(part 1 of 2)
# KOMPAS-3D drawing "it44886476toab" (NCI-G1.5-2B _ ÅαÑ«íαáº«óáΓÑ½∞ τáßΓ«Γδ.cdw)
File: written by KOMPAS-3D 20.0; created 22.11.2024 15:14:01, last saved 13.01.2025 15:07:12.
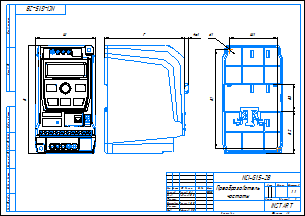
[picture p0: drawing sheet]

Sheet 1: A3, landscape

Document properties: Полное имя файла: P:\INSTART\Технический отдел\ОР\Прочие задачи\КД на номенклатурный ряд\КД на типоразмеры ПЧ\NCI\NCI-G1.5-2B\NCI-G1.5-2B _ Преобразователь частоты.cdw; Автор: admin

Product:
- Part/product: it44886476toab
    Масса: 2.32322
  - Body: Тело 2
      Масса: 0.00113358
  - Body: Тело 3
      Масса: 0.00113358
  - Body: Тело 4
      Масса: 0.000355433
  - Body: Тело 6
      Масса: 0.000355433
  - Body: Тело 7
      Масса: 0.000703761
  - Body: Тело 8
      Масса: 0.000703761
  - Body: Тело 10
      Масса: 0.0160396
  - Body: Тело 11
      Масса: 0.000703761
  - Body: Тело 13
      Масса: 0.000703761
  - Body: Тело 14
      Масса: 0.000703761
  - Body: Тело 18
      Масса: 0.0117014
  - Body: Тело 20
      Масса: 0.120334
  - Body: Тело 21
      Масса: 0.0864411
  - Body: Тело 22
      Масса: 0.0636504
  - Body: Тело 25
      Масса: 0.00135688
  - Body: Тело 26
      Масса: 0.00135688
  - Body: Тело 27
      Масса: 0.00135688
  - Body: Тело 30
      Масса: 0.000935996
  - Body: Тело 34
      Масса: 0.00831628
  - Body: Тело 36
      Масса: 0.0668131
  - Body: Тело 37
      Масса: 0.0343584
  - Body: Тело 39
      Масса: 0.0119524
  - Body: Тело 40
      Масса: 0.0119524
  - Body: Тело 42
      Масса: 0.0119524
  - Body: Тело 43
      Масса: 0.0119524
  - Body: Тело 46
      Масса: 0.0119034
  - Body: Тело 47
      Масса: 0.551587
  - Body: Тело 51
      Масса: 1.32696e-05
  - Body: Тело 54
      Масса: 1.32696e-05
  - Body: Тело 55
      Масса: 1.32696e-05
  - Body: Тело 56
      Масса: 1.32696e-05
  - Body: Тело 58
      Масса: 1.32696e-05
  - Body: Тело 61
      Масса: 1.32696e-05
  - Body: Тело 57
      Масса: 1.32696e-05
  - Body: Тело 63
      Масса: 1.65581e-05
  - Body: Тело 66
      Масса: 1.65581e-05
  - Body: Тело 67
      Масса: 1.65581e-05
  - Body: Тело 68
      Масса: 1.65581e-05
  - Body: Тело 69
      Масса: 1.65581e-05
  - Body: Тело 73
      Масса: 1.65581e-05
  - Body: Тело 48
      Масса: 0.00853877
  - Body: Тело 74
      Масса: 1.65581e-05
  - Body: Тело 78
      Масса: 1.65581e-05
  - Body: Тело 79
      Масса: 1.32696e-05
  - Body: Тело 80
      Масса: 1.32696e-05
  - Body: Тело 82
      Масса: 1.32696e-05
  - Body: Тело 83
      Масса: 1.32696e-05
  - Body: Тело 84
      Масса: 1.32696e-05
  - Body: Тело 87
      Масса: 0.000966482
  - Body: Тело 88
      Масса: 0.000873873
  - Body: Тело 15
      Масса: 0.000703761
  - Body: Тело 91
      Масса: 0.0246688
  - Body: Тело 92
      Масса: 3.83377e-05
  - Body: Тело 94
      Масса: 0.00554276
  - Body: Тело 96
      Масса: 0.00181049
  - Body: Тело 101
      Масса: 1.32696e-05
  - Body: Тело 90
      Масса: 0.000966482
  - Body: Тело 102
      Масса: 1.32696e-05
  - Body: Тело 104
      Масса: 1.32696e-05
  - Body: Тело 107
      Масса: 1.32696e-05
  - Body: Тело 108
      Масса: 1.32696e-05
  - Body: Тело 111
      Масса: 0.000194606
  - Body: Тело 115
      Масса: 0.000413213
  - Body: Тело 123
      Масса: 1.65581e-05
  - Body: Тело 127
      Масса: 1.32696e-05
  - Body: Тело 128
      Масса: 1.32696e-05
  - Body: Тело 129
      Масса: 1.32696e-05
  - Body: Тело 112
      Масса: 0.000413213
  - Body: Тело 130
      Масса: 1.32696e-05
  - Body: Тело 16
      Масса: 0.000703761
  - Body: Тело 131
      Масса: 1.32696e-05
  - Body: Тело 132
      Масса: 1.32696e-05
  - Body: Тело 133
      Масса: 1.32696e-05
  - Body: Тело 38
      Масса: 0.00631989
  - Body: Тело 135
      Масса: 1.32696e-05
  - Body: Тело 136
      Масса: 1.32696e-05
  - Body: Тело 142
      Масса: 0.000213463
  - Body: Тело 144
      Масса: 1.32696e-05
  - Body: Тело 62
      Масса: 1.32696e-05
  - Body: Тело 24
      Масса: 0.0110484
  - Body: Тело 147
      Масса: 1.32696e-05
  - Body: Тело 148
      Масса: 1.32696e-05
  - Body: Тело 154
      Масса: 1.32696e-05
  - Body: Тело 156
      Масса: 1.32696e-05
  - Body: Тело 158
      Масса: 1.32696e-05
  - Body: Тело 116
      Масса: 0.000413213
  - Body: Тело 159
      Масса: 1.32696e-05
  - Body: Тело 165
      Масса: 1.65581e-05
  - Body: Тело 166
      Масса: 1.32696e-05
  - Body: Тело 140
      Масса: 0.000213463
  - Body: Тело 169
      Масса: 1.32696e-05
  - Body: Тело 171
      Масса: 1.32696e-05
  - Body: Тело 153
      Масса: 1.32696e-05
  - Body: Тело 172
      Масса: 1.65581e-05
  - Body: Тело 173
      Масса: 1.32696e-05
  - Body: Тело 137
      Масса: 1.32696e-05
  - Body: Тело 45
      Масса: 0.0267013
  - Body: Тело 175
      Масса: 1.32696e-05
  - Body: Тело 177
      Масса: 1.32696e-05
  - Body: Тело 50
      Масса: 0.00101975
  - Body: Тело 44
      Масса: 0.0119524
  - Body: Тело 178
      Масса: 1.32696e-05
  - Body: Тело 179
      Масса: 1.32696e-05
  - Body: Тело 181
      Масса: 1.32696e-05
  - Body: Тело 182
      Масса: 1.32696e-05
  - Body: Тело 183
      Масса: 1.32696e-05
  - Body: Тело 188
      Масса: 1.32696e-05
  - Body: Тело 189
      Масса: 1.32696e-05
  - Body: Тело 192
      Масса: 1.32696e-05
  - Body: Тело 195
      Масса: 1.32696e-05
  - Body: Тело 197
      Масса: 1.32696e-05
  - Body: Тело 198
      Масса: 1.32696e-05
  - Body: Тело 199
      Масса: 1.32696e-05
  - Body: Тело 29
      Масса: 0.00135688
  - Body: Тело 201
      Масса: 1.32696e-05
  - Body: Тело 202
      Масса: 1.32696e-05
  - Body: Тело 205
      Масса: 1.32696e-05
  - Body: Тело 208
      Масса: 1.7366e-05
  - Body: Тело 209
      Масса: 1.32696e-05
  - Body: Тело 211
      Масса: 1.32696e-05
  - Body: Тело 212
      Масса: 1.32696e-05
  - Body: Тело 214
      Масса: 1.32696e-05
  - Body: Тело 9
      Масса: 0.000703761
  - Body: Тело 215
      Масса: 1.65581e-05
  - Body: Тело 217
      Масса: 1.32696e-05
  - Body: Тело 218
      Масса: 1.32696e-05
  - Body: Тело 219
      Масса: 1.32696e-05
  - Body: Тело 220
      Масса: 1.32696e-05
  - Body: Тело 221
      Масса: 1.65581e-05
  - Body: Тело 223
      Масса: 1.32696e-05
  - Body: Тело 162
      Масса: 1.65581e-05
  - Body: Тело 224
      Масса: 1.32696e-05
  - Body: Тело 228
      Масса: 1.32696e-05
  - Body: Тело 184
      Масса: 1.32696e-05
  - Body: Тело 230
      Масса: 1.32696e-05
  - Body: Тело 231
      Масса: 0.00398049
  - Body: Тело 232
      Масса: 5.48304e-05
  - Body: Тело 233
      Масса: 1.7366e-05
  - Body: Тело 1
      Масса: 0.00113358
  - Body: Тело 237
      Масса: 1.7366e-05
  - Body: Тело 141
      Масса: 0.000213463
  - Body: Тело 241
      Масса: 0.000424983
  - Body: Тело 65
      Масса: 1.65581e-05
  - Body: Тело 242
      Масса: 1.65581e-05
  - Body: Тело 243
      Масса: 1.65581e-05
  - Body: Тело 245
      Масса: 1.65581e-05
  - Body: Тело 234
      Масса: 1.7366e-05
  - Body: Тело 114
      Масса: 0.000413213
  - Body: Тело 19
      Масса: 0.0117014
  - Body: Тело 248
      Масса: 1.7366e-05
  - Body: Тело 249
      Масса: 1.7366e-05
  - Body: Тело 250
      Масса: 1.7366e-05
  - Body: Тело 254
      Масса: 1.32696e-05
  - Body: Тело 255
      Масса: 1.7366e-05
  - Body: Тело 119
      Масса: 0.000413213
  - Body: Тело 256
      Масса: 1.7366e-05
  - Body: Тело 167
      Масса: 1.32696e-05
  - Body: Тело 260
      Масса: 1.7366e-05
  - Body: Тело 261
      Масса: 3.83377e-05
  - Body: Тело 170
      Масса: 1.32696e-05
  - Body: Тело 463
      Масса: 0.000404362
  - Body: Тело 226
      Масса: 0.000413213
  - Body: Тело 464
      Масса: 0.00829425
  - Body: Тело 268
      Масса: 5.48304e-05
  - Body: Тело 467
      Масса: 0.00436982
  - Body: Тело 475
      Масса: 1.51773e-05
  - Body: Тело 451
      Масса: 6.34685e-05
  - Body: Тело 478
      Масса: 1.51773e-05
  - Body: Тело 465
      Масса: 0.00829114
  - Body: Тело 383
      Масса: 0.000340816
  - Body: Тело 125
      Масса: 1.65581e-05
  - Body: Тело 643
      Масса: 0.000158536
  - Body: Тело 514
      Масса: 1.51773e-05
  - Body: Тело 483
      Масса: 1.51773e-05
  - Body: Тело 486
      Масса: 0.000158536
  - Body: Тело 581
      Масса: 1.65581e-05
  - Body: Тело 490
      Масса: 1.51773e-05
  - Body: Тело 491
      Масса: 1.65581e-05
  - Body: Тело 433
      Масса: 0.000118347
  - Body: Тело 496
      Масса: 1.51773e-05
  - Body: Тело 437
      Масса: 0.00113358
  - Body: Тело 535
      Масса: 1.52051e-05
  - Body: Тело 498
      Масса: 1.51773e-05
  - Body: Тело 60
      Масса: 1.32696e-05
  - Body: Тело 369
      Масса: 1.32696e-05
  - Body: Тело 501
      Масса: 1.51773e-05
  - Body: Тело 503
      Масса: 1.51773e-05
  - Body: Тело 447
      Масса: 0.000307437
  - Body: Тело 187
      Масса: 1.32696e-05
  - Body: Тело 12
      Масса: 0.000703761
  - Body: Тело 507
      Масса: 1.51773e-05
  - Body: Тело 174
      Масса: 1.65581e-05
  - Body: Тело 587
      Масса: 1.32696e-05
  - Body: Тело 155
      Масса: 1.32696e-05
  - Body: Тело 512
      Масса: 1.51773e-05
  - Body: Тело 515
      Масса: 0.00507372
  - Body: Тело 510
      Масса: 1.51773e-05
  - Body: Тело 487
      Масса: 1.65581e-05
  - Body: Тело 432
      Масса: 0.000118347
  - Body: Тело 524
      Масса: 1.65581e-05
  - Body: Тело 637
      Масса: 1.51773e-05
  - Body: Тело 519
      Масса: 1.7366e-05
  - Body: Тело 427
      Масса: 1.32696e-05
  - Body: Тело 520
      Масса: 5.48304e-05
  - Body: Тело 326
      Масса: 1.32696e-05
  - Body: Тело 509
      Масса: 1.51773e-05
  - Body: Тело 571
      Масса: 0.00166679
  - Body: Тело 521
      Масса: 1.32696e-05
  - Body: Тело 522
      Масса: 1.65581e-05
  - Body: Тело 49
      Масса: 0.00944
  - Body: Тело 319
      Масса: 1.32696e-05
  - Body: Тело 458
      Масса: 1.51773e-05
  - Body: Тело 523
      Масса: 0.000255388
  - Body: Тело 191
      Масса: 1.32696e-05
  - Body: Тело 590
      Масса: 1.32696e-05
  - Body: Тело 599
      Масса: 7.12116e-06
  - Body: Тело 528
      Масса: 0.000141095
  - Body: Тело 64
      Масса: 1.65581e-05
  - Body: Тело 468
      Масса: 0.0253857
  - Body: Тело 216
      Масса: 0.000280294
  - Body: Тело 443
      Масса: 0.00113358
  - Body: Тело 239
      Масса: 5.48304e-05
  - Body: Тело 200
      Масса: 1.32696e-05
  - Body: Тело 579
      Масса: 0.00017125
  - Body: Тело 529
      Масса: 5.61948e-05
  - Body: Тело 493
      Масса: 1.51773e-05
  - Body: Тело 532
      Масса: 5.61948e-05
  - Body: Тело 343
      Масса: 0.00166679
  - Body: Тело 616
      Масса: 1.63919e-05
  - Body: Тело 462
      Масса: 0.000404362
  - Body: Тело 542
      Масса: 0.000158536
  - Body: Тело 543
      Масса: 0.000158536
  - Body: Тело 615
      Масса: 1.63919e-05
  - Body: Тело 149
      Масса: 1.32696e-05
  - Body: Тело 146
      Масса: 1.32696e-05
  - Body: Тело 469
      Масса: 0.0113891
  - Body: Тело 544
      Масса: 0.000158536
  - Body: Тело 295
      Масса: 1.65581e-05
  - Body: Тело 120
      Масса: 0.000413213
  - Body: Тело 352
      Масса: 2.90876e-05
  - Body: Тело 502
      Масса: 1.51773e-05
  - Body: Тело 461
      Масса: 0.000404362
  - Body: Тело 145
      Масса: 1.32696e-05
  - Body: Тело 545
      Масса: 1.51773e-05
  - Body: Тело 506
      Масса: 1.51773e-05
  - Body: Тело 71
      Масса: 1.65581e-05
  - Body: Тело 41
      Масса: 0.0119524
  - Body: Тело 547
      Масса: 0.000255388
  - Body: Тело 614
      Масса: 1.63919e-05
  - Body: Тело 257
      Масса: 1.7366e-05
  - Body: Тело 549
      Масса: 0.000255388
  - Body: Тело 204
      Масса: 1.32696e-05
  - Body: Тело 35
      Масса: 0.262997
  - Body: Тело 421
      Масса: 1.7366e-05
  - Body: Тело 258
      Масса: 1.7366e-05
  - Body: Тело 504
      Масса: 1.51773e-05
  - Body: Тело 366
      Масса: 1.7366e-05
  - Body: Тело 592
      Масса: 7.12116e-06
  - Body: Тело 32
      Масса: 0.0135217
  - Body: Тело 550
      Масса: 0.000255388
  - Body: Тело 157
      Масса: 1.32696e-05
  - Body: Тело 126
      Масса: 0.000512664
  - Body: Тело 314
      Масса: 1.7366e-05
  - Body: Тело 247
      Масса: 1.7366e-05
  - Body: Тело 23
      Масса: 0.0243258
  - Body: Тело 595
      Масса: 1.32696e-05
  - Body: Тело 534
      Масса: 1.32696e-05
  - Body: Тело 552
      Масса: 4.06595e-05
  - Body: Тело 176
      Масса: 1.32696e-05
  - Body: Тело 553
      Масса: 4.06595e-05
  - Body: Тело 28
      Масса: 0.00135688
  - Body: Тело 330
      Масса: 1.7366e-05
  - Body: Тело 190
      Масса: 1.32696e-05
  - Body: Тело 416
      Масса: 1.7366e-05
  - Body: Тело 435
      Масса: 0.00113358
  - Body: Тело 634
      Масса: 1.51773e-05
  - Body: Тело 555
      Масса: 0.00166679
  - Body: Тело 556
      Масса: 0.00166679
  - Body: Тело 602
      Масса: 5.61948e-05
  - Body: Тело 630
      Масса: 1.51773e-05
  - Body: Тело 558
      Масса: 0.00726683
  - Body: Тело 505
      Масса: 1.51773e-05
  - Body: Тело 500
      Масса: 1.51773e-05
  - Body: Тело 72
      Масса: 1.65581e-05
  - Body: Тело 279
      Масса: 1.32696e-05
  - Body: Тело 298
      Масса: 3.64495e-05
  - Body: Тело 168
      Масса: 1.32696e-05
  - Body: Тело 495
      Масса: 1.51773e-05
  - Body: Тело 336
      Масса: 3.64028e-05
  - Body: Тело 629
      Масса: 1.51773e-05
  - Body: Тело 263
      Масса: 1.7366e-05
  - Body: Тело 610
      Масса: 0.00166679
  - Body: Тело 609
      Масса: 1.7366e-05
  - Body: Тело 596
      Масса: 1.32696e-05
  - Body: Тело 538
      Масса: 1.51773e-05
  - Body: Тело 476
      Масса: 1.51773e-05
  - Body: Тело 227
      Масса: 1.32696e-05
  - Body: Тело 382
      Масса: 5.48304e-05
  - Body: Тело 470
      Масса: 0.00329329
  - Body: Тело 341
      Масса: 0.00166679
  - Body: Тело 426
      Масса: 1.32696e-05
  - Body: Тело 513
      Масса: 1.51773e-05
  - Body: Тело 236
      Масса: 1.7366e-05
  - Body: Тело 585
      Масса: 4.06595e-05
  - Body: Тело 649
      Масса: 0.00426189
  - Body: Тело 531
      Масса: 5.61948e-05
  - Body: Тело 627
      Масса: 0.000255388
  - Body: Тело 621
      Масса: 1.32696e-05
  - Body: Тело 349
      Масса: 1.7366e-05
  - Body: Тело 580
      Масса: 1.32696e-05
  - Body: Тело 631
      Масса: 1.51773e-05
  - Body: Тело 185
      Масса: 1.32696e-05
  - Body: Тело 117
      Масса: 0.000413213
  - Body: Тело 623
      Масса: 1.32696e-05
  - Body: Тело 605
      Масса: 5.61948e-05
  - Body: Тело 400
      Масса: 1.7366e-05
  - Body: Тело 139
      Масса: 0.000194606
  - Body: Тело 492
      Масса: 1.51773e-05
  - Body: Тело 612
      Масса: 0.000158536
  - Body: Тело 403
      Масса: 1.7366e-05
  - Body: Тело 460
      Масса: 3.90329e-05
  - Body: Тело 608
      Масса: 0.00166679
  - Body: Тело 635
      Масса: 1.65581e-05
  - Body: Тело 264
      Масса: 1.7366e-05
  - Body: Тело 646
      Масса: 0.000137594
  - Body: Тело 110
      Масса: 1.32696e-05
  - Body: Тело 302
      Масса: 1.65581e-05
  - Body: Тело 151
      Масса: 1.65581e-05
  - Body: Тело 497
      Масса: 1.51773e-05
  - Body: Тело 620
      Масса: 1.7366e-05
  - Body: Тело 518
      Масса: 0.00166679
  - Body: Тело 633
      Масса: 1.51773e-05
  - Body: Тело 564
      Масса: 4.06595e-05
  - Body: Тело 641
      Масса: 3.90329e-05
  - Body: Тело 494
      Масса: 1.51773e-05
  - Body: Тело 280
      Масса: 1.32696e-05
  - Body: Тело 81
      Масса: 1.32696e-05
  - Body: Тело 482
      Масса: 1.51773e-05
  - Body: Тело 594
      Масса: 1.32696e-05
  - Body: Тело 561
      Масса: 1.65581e-05
  - Body: Тело 253
      Масса: 1.7366e-05
  - Body: Тело 164
      Масса: 1.32696e-05
  - Body: Тело 525
      Масса: 0.000213463
  - Body: Тело 618
      Масса: 1.63919e-05
  - Body: Тело 642
      Масса: 3.90329e-05
  - Body: Тело 113
      Масса: 0.000413213
  - Body: Тело 546
      Масса: 0.000255388
  - Body: Тело 225
      Масса: 1.32696e-05
  - Body: Тело 138
      Масса: 2.23009e-05
  - Body: Тело 284
      Масса: 1.7366e-05
  - Body: Тело 485
      Масса: 0.000158536
  - Body: Тело 456
      Масса: 1.51773e-05
  - Body: Тело 489
      Масса: 1.51773e-05
  - Body: Тело 638
      Масса: 1.7366e-05
  - Body: Тело 563
      Масса: 4.06595e-05
  - Body: Тело 566
      Масса: 1.32696e-05
  - Body: Тело 160
      Масса: 1.32696e-05
  - Body: Тело 511
      Масса: 1.51773e-05
  - Body: Тело 541
      Масса: 0.000158536
  - Body: Тело 306
      Масса: 1.65581e-05
  - Body: Тело 356
      Масса: 1.65581e-05
  - Body: Тело 591
      Масса: 7.12116e-06
  - Body: Тело 313
      Масса: 1.7366e-05
  - Body: Тело 471
      Масса: 0.00329327
  - Body: Тело 289
      Масса: 1.7366e-05
  - Body: Тело 607
      Масса: 1.32696e-05
  - Body: Тело 603
      Масса: 5.61948e-05
  - Body: Тело 600
      Масса: 5.61948e-05
  - Body: Тело 121
      Масса: 0.000413213
  - Body: Тело 624
      Масса: 1.32696e-05
  - Body: Тело 527
      Масса: 0.000141095
  - Body: Тело 622
      Масса: 1.32696e-05
  - Body: Тело 484
      Масса: 0.000158536
  - Body: Тело 601
      Масса: 5.61948e-05
  - Body: Тело 296
      Масса: 3.6965e-05
  - Body: Тело 540
      Масса: 1.51773e-05
  - Body: Тело 210
      Масса: 1.32696e-05
  - Body: Тело 611
      Масса: 0.000158536
  - Body: Тело 161
      Масса: 1.32696e-05
  - Body: Тело 650
      Масса: 0.00426189
  - Body: Тело 604
      Масса: 5.61948e-05
  - Body: Тело 342
      Масса: 0.00166679
  - Body: Тело 251
      Масса: 1.7366e-05
  - Body: Тело 194
      Масса: 1.32696e-05
  - Body: Тело 568
      Масса: 1.32696e-05
  - Body: Тело 150
      Масса: 1.32696e-05
  - Body: Тело 640
      Масса: 1.63919e-05
  - Body: Тело 440
      Масса: 0.000355433
  - Body: Тело 499
      Масса: 1.51773e-05
  - Body: Тело 589
      Масса: 1.32696e-05
  - Body: Тело 361
      Масса: 1.32696e-05
  - Body: Тело 619
      Масса: 1.32696e-05
  - Body: Тело 405
      Масса: 1.32696e-05
  - Body: Тело 551
      Масса: 0.000255388
  - Body: Тело 598
      Масса: 7.12116e-06
  - Body: Тело 583
      Масса: 4.06595e-05
  - Body: Тело 411
      Масса: 5.48304e-05
  - Body: Тело 367
      Масса: 1.32696e-05
  - Body: Тело 488
      Масса: 1.51773e-05
  - Body: Тело 163
      Масса: 1.32696e-05
  - Body: Тело 109
      Масса: 1.32696e-05
  - Body: Тело 408
      Масса: 5.48304e-05
  - Body: Тело 593
      Масса: 1.32696e-05
  - Body: Тело 387
      Масса: 1.32696e-05
  - Body: Тело 613
      Масса: 1.63919e-05
  - Body: Тело 597
      Масса: 7.12116e-06
  - Body: Тело 118
      Масса: 0.000413213
  - Body: Тело 565
      Масса: 4.06595e-05
  - Body: Тело 632
      Масса: 1.51773e-05
  - Body: Тело 379
      Масса: 1.32696e-05
  - Body: Тело 562
      Масса: 0.000382752
  - Body: Тело 262
      Масса: 1.7366e-05
  - Body: Тело 586
      Масса: 1.32696e-05
  - Body: Тело 647
      Масса: 0.00426189
  - Body: Тело 533
      Масса: 5.61948e-05
  - Body: Тело 472
      Масса: 0.00329327
  - Body: Тело 409
      Масса: 5.48304e-05
  - Body: Тело 548
      Масса: 2.98222e-05
  - Body: Тело 474
      Масса: 1.51773e-05
  - Body: Тело 363
      Масса: 1.32696e-05
  - Body: Тело 276
      Масса: 1.7366e-05
  - Body: Тело 588
      Масса: 1.32696e-05
  - Body: Тело 70
      Масса: 1.65581e-05
  - Body: Тело 584
      Масса: 4.06595e-05
  - Body: Тело 644
      Масса: 0.000158536
  - Body: Тело 625
      Масса: 1.32696e-05
  - Body: Тело 213
      Масса: 1.32696e-05
  - Body: Тело 275
      Масса: 1.7366e-05
  - Body: Тело 320
      Масса: 1.32696e-05
  - Body: Тело 399
      Масса: 1.32696e-05
  - Body: Тело 574
      Масса: 4.06595e-05
  - Body: Тело 85
      Масса: 1.32696e-05
  - Body: Тело 576
      Масса: 1.32696e-05
  - Body: Тело 575
      Масса: 1.32696e-05
  - Body: Тело 376
      Масса: 1.32696e-05
  - Body: Тело 316
      Масса: 1.32696e-05
  - Body: Тело 449
      Масса: 0.0658364
  - Body: Тело 152
      Масса: 1.32696e-05
  - Body: Тело 559
      Масса: 1.65581e-05
  - Body: Тело 645
      Масса: 1.32696e-05
  - Body: Тело 207
      Масса: 1.32696e-05
  - Body: Тело 567
      Масса: 1.32696e-05
  - Body: Тело 572
      Масса: 1.32696e-05
  - Body: Тело 203
      Масса: 1.32696e-05
  - Body: Тело 582
      Масса: 1.65581e-05
  - Body: Тело 134
      Масса: 1.32696e-05
  - Body: Тело 626
      Масса: 1.32696e-05
  - Body: Тело 578
      Масса: 1.32696e-05
  - Body: Тело 569
      Масса: 1.32696e-05
  - Body: Тело 557
      Масса: 0.00166679
  - Body: Тело 459
      Масса: 3.90329e-05
  - Body: Тело 457
      Масса: 1.51773e-05
  - Body: Тело 539
      Масса: 1.51773e-05
  - Body: Тело 455
      Масса: 1.51773e-05
  - Body: Тело 428
      Масса: 0.146258
  - Body: Тело 454
      Масса: 0.000382752
  - Body: Тело 453
      Масса: 1.63919e-05
  - Body: Тело 417
      Масса: 1.32696e-05
  - Body: Тело 517
      Масса: 0.00106884
  - Body: Тело 418
      Масса: 1.7366e-05
  - Body: Тело 401
      Масса: 1.32696e-05
  - Body: Тело 53
      Масса: 1.32696e-05
  - Body: Тело 452
      Масса: 1.63919e-05
  - Body: Тело 315
      Масса: 1.7366e-05
  - Body: Тело 222
      Масса: 1.32696e-05
  - Body: Тело 450
      Масса: 6.34685e-05
  - Body: Тело 481
      Масса: 1.51773e-05
  - Body: Тело 448
      Масса: 0.000307437
  - Body: Тело 193
      Масса: 1.32696e-05
  - Body: Тело 392
      Масса: 1.32696e-05
  - Body: Тело 577
      Масса: 1.7366e-05
  - Body: Тело 508
      Масса: 1.51773e-05
  - Body: Тело 106
      Масса: 1.32696e-05
  - Body: Тело 438
      Масса: 0.000355433
  - Body: Тело 445
      Масса: 0.00113358
  - Body: Тело 246
      Масса: 1.65581e-05
  - Body: Тело 444
      Масса: 0.000355433
  - Body: Тело 554
      Масса: 4.06595e-05
  - Body: Тело 442
      Масса: 0.000355433
  - Body: Тело 441
      Масса: 0.00113358
  - Body: Тело 323
      Масса: 1.32696e-05
  - Body: Тело 606
      Масса: 0.000137594
  - Body: Тело 439
      Масса: 0.00113358
  - Body: Тело 436
      Масса: 0.000355433
  - Body: Тело 344
      Масса: 1.32696e-05
  - Body: Тело 124
      Масса: 1.65581e-05
  - Body: Тело 5
      Масса: 0.000355433
  - Body: Тело 434
      Масса: 0.000355433
  - Body: Тело 329
      Масса: 1.32696e-05
  - Body: Тело 364
      Масса: 1.32696e-05
  - Body: Тело 431
      Масса: 0.146258
  - Body: Тело 345
      Масса: 1.32696e-05
  - Body: Тело 350
      Масса: 1.7366e-05
  - Body: Тело 430
      Масса: 0.146258
  - Body: Тело 334
      Масса: 1.7366e-05
  - Body: Тело 429
      Масса: 0.146258
  - Body: Тело 206
      Масса: 1.32696e-05
  - Body: Тело 271
      Масса: 1.32696e-05
  - Body: Тело 365
      Масса: 1.32696e-05
  - Body: Тело 425
      Масса: 1.32696e-05
  - Body: Тело 305
      Масса: 1.65581e-05
  - Body: Тело 98
      Масса: 1.65581e-05
  - Body: Тело 424
      Масса: 1.7366e-05
  - Body: Тело 423
      Масса: 1.32696e-05
  - Body: Тело 381
      Масса: 1.7366e-05
  - Body: Тело 422
      Масса: 5.48304e-05
  - Body: Тело 186
      Масса: 1.32696e-05
  - Body: Тело 420
      Масса: 1.7366e-05
  - Body: Тело 648
      Масса: 0.00426189
  - Body: Тело 419
      Масса: 1.32696e-05
  - Body: Тело 235
      Масса: 1.7366e-05
  - Body: Тело 415
      Масса: 1.7366e-05
  - Body: Тело 537
      Масса: 0.000158536
  - Body: Тело 414
      Масса: 1.32696e-05
  - Body: Тело 413
      Масса: 1.32696e-05
  - Body: Тело 412
      Масса: 1.7366e-05
  - Body: Тело 636
      Масса: 1.65581e-05
  - Body: Тело 410
      Масса: 5.48304e-05
  - Body: Тело 97
      Масса: 0.0015961
  - Body: Тело 407
      Масса: 5.48304e-05
  - Body: Тело 52
      Масса: 1.32696e-05
  - Body: Тело 393
      Масса: 1.32696e-05
  - Body: Тело 406
      Масса: 1.65581e-05
  - Body: Тело 89
      Масса: 0.00142218
  - Body: Тело 404
      Масса: 1.32696e-05
  - Body: Тело 339
      Масса: 1.32696e-05
  - Body: Тело 59
      Масса: 1.32696e-05
  - Body: Тело 402
      Масса: 1.7366e-05
  - Body: Тело 479
      Масса: 1.51773e-05
  - Body: Тело 398
      Масса: 1.65581e-05
  - Body: Тело 397
      Масса: 1.32696e-05
  - Body: Тело 396
      Масса: 1.7366e-05
  - Body: Тело 354
      Масса: 0.000213463
  - Body: Тело 395
      Масса: 1.32696e-05
  - Body: Тело 394
      Масса: 1.32696e-05
  - Body: Тело 143
      Масса: 1.32696e-05
  - Body: Тело 390
      Масса: 1.65581e-05
  - Body: Тело 93
      Масса: 3.83377e-05
  - Body: Тело 389
      Масса: 1.65581e-05
  - Body: Тело 388
      Масса: 1.32696e-05
  - Body: Тело 229
      Масса: 1.32696e-05
  - Body: Тело 386
      Масса: 1.32696e-05
  - Body: Тело 291
      Масса: 0.000213463
  - Body: Тело 385
      Масса: 1.32696e-05
  - Body: Тело 639
      Масса: 1.63919e-05
  - Body: Тело 380
      Масса: 1.32696e-05
  - Body: Тело 322
      Масса: 1.32696e-05
  - Body: Тело 372
      Масса: 1.7366e-05
  - Body: Тело 95
      Масса: 0.000935996
  - Body: Тело 378
      Масса: 0.000413213
  - Body: Тело 259
      Масса: 1.7366e-05
  - Body: Тело 76
      Масса: 1.65581e-05
  - Body: Тело 351
      Масса: 2.90876e-05
  - Body: Тело 375
      Масса: 1.32696e-05
  - Body: Тело 373
      Масса: 1.32696e-05
  - Body: Тело 75
      Масса: 1.32696e-05
  - Body: Тело 371
      Масса: 1.7366e-05
  - Body: Тело 628
      Масса: 1.51773e-05
  - Body: Тело 333
      Масса: 1.32696e-05
  - Body: Тело 370
      Масса: 1.32696e-05
  - Body: Тело 368
      Масса: 1.32696e-05
  - Body: Тело 310
      Масса: 1.7366e-05
  - Body: Тело 86
      Масса: 1.32696e-05
  - Body: Тело 286
      Масса: 1.7366e-05
  - Body: Тело 359
      Масса: 1.7366e-05
  - Body: Тело 358
      Масса: 5.48304e-05
  - Body: Тело 466
      Масса: 0.00829114
  - Body: Тело 355
      Масса: 5.48304e-05
  - Body: Тело 353
      Масса: 1.7366e-05
  - Body: Тело 362
      Масса: 1.32696e-05
  - Body: Тело 281
      Масса: 1.32696e-05
  - Body: Тело 335
      Масса: 1.32696e-05
  - Body: Тело 346
      Масса: 1.32696e-05
  - Body: Тело 357
      Масса: 1.65581e-05
  - Body: Тело 196
      Масса: 1.32696e-05
  - Body: Тело 340
      Масса: 1.32696e-05
  - Body: Тело 570
      Масса: 4.06595e-05
  - Body: Тело 338
      Масса: 1.7366e-05
  - Body: Тело 337
      Масса: 1.7366e-05
  - Body: Тело 446
      Масса: 0.000307437
  - Body: Тело 332
      Масса: 1.7366e-05
  - Body: Тело 331
      Масса: 1.7366e-05
  - Body: Тело 301
      Масса: 1.65581e-05
  - Body: Тело 328
      Масса: 1.7366e-05
  - Body: Тело 105
      Масса: 1.32696e-05
  - Body: Тело 100
      Масса: 1.65581e-05
  - Body: Тело 31
      Масса: 0.0078835
  - Body: Тело 327
      Масса: 1.32696e-05
  - Body: Тело 617
      Масса: 1.63919e-05
  - Body: Тело 99
      Масса: 1.65581e-05
  - Body: Тело 325
      Масса: 1.32696e-05
  - Body: Тело 293
      Масса: 5.48304e-05
  - Body: Тело 288
      Масса: 1.7366e-05
  - Body: Тело 480
      Масса: 1.51773e-05
  - Body: Тело 324
      Масса: 1.32696e-05
  - Body: Тело 321
      Масса: 1.32696e-05
  - Body: Тело 318
      Масса: 1.32696e-05
  - Body: Тело 317
      Масса: 1.32696e-05
  - Body: Тело 312
      Масса: 5.48304e-05
  - Body: Тело 560
      Масса: 1.65581e-05
  - Body: Тело 122
      Масса: 1.65581e-05
  - Body: Тело 311
      Масса: 5.48304e-05
  - Body: Тело 473
      Масса: 0.00425494
  - Body: Тело 309
      Масса: 1.32696e-05
  - Body: Тело 240
      Масса: 1.7366e-05
  - Body: Тело 180
      Масса: 1.32696e-05
  - Body: Тело 308
      Масса: 0.000413213
  - Body: Тело 307
      Масса: 0.000213463
  - Body: Тело 304
      Масса: 1.65581e-05
  - Body: Тело 347
      Масса: 1.32696e-05
  - Body: Тело 360
      Масса: 1.32696e-05
  - Body: Тело 384
      Масса: 5.48304e-05
  - Body: Тело 516
      Масса: 0.00507377
  - Body: Тело 303
      Масса: 1.65581e-05
  - Body: Тело 300
      Масса: 1.65581e-05
  - Body: Тело 283
      Масса: 1.7366e-05
  - Body: Тело 299
      Масса: 3.64028e-05
  - Body: Тело 297
      Масса: 3.64631e-05
  - Body: Тело 294
      Масса: 0.000413213
  - Body: Тело 252
      Масса: 5.48304e-05
  - Body: Тело 33
      Масса: 0.00516019
  - Body: Тело 292
      Масса: 1.7366e-05
  - Body: Тело 269
      Масса: 5.48304e-05
  - Body: Тело 290
      Масса: 0.000413213
  - Body: Тело 287
      Масса: 1.32696e-05
  - Body: Тело 285
      Масса: 5.48304e-05
  - Body: Тело 391
      Масса: 1.32696e-05
  - Body: Тело 526
      Масса: 5.61948e-05
  - Body: Тело 477
      Масса: 1.51773e-05
  - Body: Тело 282
      Масса: 1.7366e-05
  - Body: Тело 278
      Масса: 1.7366e-05
  - Body: Тело 530
      Масса: 5.61948e-05
  - Body: Тело 277
      Масса: 1.7366e-05
  - Body: Тело 274
      Масса: 1.7366e-05
  - Body: Тело 238
      Масса: 1.7366e-05
  - Body: Тело 273
      Масса: 5.48304e-05
  - Body: Тело 272
      Масса: 1.7366e-05
  - Body: Тело 377
      Масса: 1.65581e-05
  - Body: Тело 536
      Масса: 0.000158536
  - Body: Тело 244
      Масса: 1.65581e-05
  - Body: Тело 77
      Масса: 1.32696e-05
  - Body: Тело 270
      Масса: 1.7366e-05
  - Body: Тело 348
      Масса: 1.32696e-05
  - Body: Тело 573
      Масса: 4.06595e-05
  - Body: Тело 103
      Масса: 1.32696e-05
  - Body: Тело 267
      Масса: 1.7366e-05
  - Body: Тело 266
      Масса: 1.7366e-05
  - Body: Тело 265
      Масса: 1.32696e-05
  - Body: Тело 374
      Масса: 5.48304e-05
  - Body: Тело 17
      Масса: 0.0117014

Title block, sheet 1: Наименование: Преобразователь / частоты; designation: NCI-G1.5-2B; Количество листов документа: 1; organisation: INSTART; cell 10: Согласовано; Форматы листов документа: A3; stored path: P:\INSTART\Технический отдел\ОР\Прочие задачи\КД на номенклатурный ряд\КД на типоразмеры ПЧ\NCI\NCI-G0.75_P1.5-4B\NCI-G0.75_P1.5-4B _ Преобразователь частоты.cdw; Разработал: Уралов Д.А.; Проверил: Андреев Н.В.; Подписал: Смелков Ж.Е.; Утвердил: Ефремов И.Н.; Разработал, date: 13.01.25

Views: Вид 1
Referenced files in C:\Уралов Работа\Уралов (локальная)\ПЧ\! Китай 3Д-модель NCI\NCI 0.75-2.2 4B\: NCI 0.75-2.2 4B.m3d
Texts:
  Кривая без истории:10000
  Кривая без истории:10001
  Кривая без истории:10002
  Кривая без истории:10003
  Кривая без истории:10004
  Кривая без истории:10005
  Кривая без истории:10006
  Кривая без истории:10007
  Кривая без истории:10008
  Кривая без истории:10009
  Кривая без истории:10010
  Кривая без истории:10011
  Кривая без истории:10012
  Кривая без истории:10013
  Кривая без истории:10014
  Кривая без истории:10015
  Кривая без истории:10016
  Кривая без истории:10017
  Кривая без истории:10018
  Кривая без истории:10019
  Кривая без истории:10020
  Кривая без истории:10021
  Кривая без истории:10022
  Кривая без истории:10023
  Кривая без истории:10024
  Кривая без истории:10025
  Кривая без истории:10026
  Кривая без истории:10027
  Кривая без истории:10028
  Кривая без истории:10029
  Кривая без истории:10030
  Кривая без истории:10031
  Кривая без истории:10032
  Кривая без истории:10033
  Кривая без истории:10034
  Кривая без истории:10035
  Кривая без истории:10036
  Кривая без истории:10037
  Кривая без истории:10038
  Кривая без истории:10039
  Кривая без истории:10040
  Кривая без истории:10041
  Кривая без истории:10042
  Кривая без истории:10043
  Кривая без истории:10044
  Кривая без истории:10045
  Кривая без истории:10046
  Кривая без истории:10047
  Кривая без истории:10048
  Кривая без истории:10049
  Кривая без истории:10050
  Кривая без истории:10051
  Кривая без истории:10052
  Кривая без истории:10053
  Кривая без истории:10054
  Кривая без истории:10055
  Кривая без истории:10056
  Кривая без истории:10057
  Кривая без истории:10058
  Кривая без истории:10059
  Кривая без истории:10060
  Кривая без истории:10061
  Кривая без истории:10062
  Кривая без истории:10063
  Кривая без истории:10064
  Кривая без истории:10065
  Кривая без истории:10066
  Кривая без истории:10067
  Кривая без истории:10068
  Кривая без истории:10069
  Кривая без истории:10070
  Кривая без истории:10071
  Кривая без истории:10072
  Кривая без истории:10073
  Кривая без истории:10074
  Кривая без истории:10075
  Кривая без истории:10076
  Кривая без истории:10077
  Кривая без истории:10078
  Кривая без истории:10079
  Кривая без истории:10080
  Кривая без истории:10081
  Кривая без истории:10082
  Кривая без истории:10083
  Кривая без истории:10084
  Кривая без истории:10085
  Кривая без истории:10086
  Кривая без истории:10087
  Кривая без истории:10088
  Кривая без истории:10089
  Кривая без истории:10090
  Кривая без истории:10091
  Кривая без истории:10092
  Кривая без истории:10093
  Кривая без истории:10094
  Кривая без истории:10095
  Кривая без истории:10096
  Кривая без истории:10097
  Кривая без истории:10098
  Кривая без истории:10099
  Кривая без истории:10100
  Кривая без истории:10101
  Кривая без истории:10102
  Кривая без истории:10103
  Кривая без истории:10104
  Кривая без истории:10105
  Кривая без истории:10106
  Кривая без истории:10107
  Кривая без истории:10108
  Кривая без истории:10109
  Кривая без истории:10110
  Кривая без истории:10111
  Кривая без истории:10112
  Кривая без истории:10113
  Кривая без истории:10114
  Кривая без истории:10115
  Кривая без истории:10116
  Кривая без истории:10117
  Кривая без истории:10118
  Кривая без истории:10119
  Кривая без истории:10120
  Кривая без истории:10121
  Кривая без истории:10122
  Кривая без истории:10123
  Кривая без истории:10124
  Кривая без истории:10125
  Кривая без истории:10126
  Кривая без истории:10127
  Кривая без истории:10128
  Кривая без истории:10129
  Кривая без истории:10130
  Кривая без истории:10131
  Кривая без истории:10132
  Кривая без истории:10133
  Кривая без истории:10134
  Кривая без истории:10135
  Кривая без истории:10136
  Кривая без истории:10137
  Кривая без истории:10138
  Кривая без истории:10139
  Кривая без истории:10140
  Кривая без истории:10141
  Кривая без истории:10142
  Кривая без истории:10143
  Кривая без истории:10144
  Кривая без истории:10145
  Кривая без истории:10146
  Кривая без истории:10147
  Кривая без истории:10148
  Кривая без истории:10149
  Кривая без истории:10150
  Кривая без истории:10151
  Кривая без истории:10152
  Кривая без истории:10153
  Кривая без истории:10154
  Кривая без истории:10155
  Кривая без истории:10156
  Кривая без истории:10157
  Кривая без истории:10158
  Кривая без истории:10159
  Кривая без истории:10160
  Кривая без истории:10161
  Кривая без истории:10162
  Кривая без истории:10163
  Кривая без истории:10164
  Кривая без истории:10165
  Кривая без истории:10166
  Кривая без истории:10167
  Кривая без истории:10168
  Кривая без истории:10169
  Кривая без истории:10170
  Кривая без истории:10171
  Кривая без истории:10172
  Кривая без истории:10173
  Кривая без истории:10174
  Кривая без истории:10175
  Кривая без истории:10176
  Кривая без истории:10177
  Кривая без истории:10178
  Кривая без истории:10179
  Кривая без истории:10180
  Кривая без истории:10181
  Кривая без истории:10182
  Кривая без истории:10183
  Кривая без истории:10184
  Кривая без истории:10185
  Кривая без истории:10186
  Кривая без истории:10187
  Кривая без истории:10188
  Кривая без истории:10189
  Кривая без истории:10190
  Кривая без истории:10191
  Кривая без истории:10192
  Кривая без истории:10193
  Кривая без истории:10194
  Кривая без истории:10195
  Кривая без истории:10196
  Кривая без истории:10197
  Кривая без истории:10198
  Кривая без истории:10199
  Кривая без истории:10200
  Кривая без истории:10201
  Кривая без истории:10202
  Кривая без истории:10203
  Кривая без истории:10204
  Кривая без истории:10205
  Кривая без истории:10206
  Кривая без истории:10207
  Кривая без истории:10208
  Кривая без истории:10209
  Кривая без истории:10210
  Кривая без истории:10211
  Кривая без истории:10212
  Кривая без истории:10213
  Кривая без истории:10214
  Кривая без истории:10215
  Кривая без истории:10216
  Кривая без истории:10217
  Кривая без истории:10218
  Кривая без истории:10219
  Кривая без истории:10220
  Кривая без истории:10221
  Кривая без истории:10222
  Кривая без истории:10223
  Кривая без истории:10224
  Кривая без истории:10225
  Кривая без истории:10226
  Кривая без истории:10227
  Кривая без истории:10228
  Кривая без истории:10229
  Кривая без истории:10230
  Кривая без истории:10231
  Кривая без истории:10232
  Кривая без истории:10233
  Кривая без истории:10234
  Кривая без истории:10235
  Кривая без истории:10236
  Кривая без истории:10237
  Кривая без истории:10238
  Кривая без истории:10239
  Кривая без истории:10240
  Кривая без истории:10241
  Кривая без истории:10242
  Кривая без истории:10243
  Кривая без истории:10244
  Кривая без истории:10245
  Кривая без истории:10246
  Кривая без истории:10247
  Кривая без истории:10248
  Кривая без истории:10249
  Кривая без истории:10250
  Кривая без истории:10251
  Кривая без истории:10252
  Кривая без истории:10253
  Кривая без истории:10254
  Кривая без истории:10255
  Кривая без истории:10256
  Кривая без истории:10257
  Кривая без истории:10258
  Кривая без истории:10259
  Кривая без истории:10260
  Кривая без истории:10261
  Кривая без истории:10262
  Кривая без истории:10263
  Кривая без истории:10264
  Кривая без истории:10265
  Кривая без истории:10266
  Кривая без истории:10267
  Кривая без истории:10268
  Кривая без истории:10269
  Кривая без истории:10270
  Кривая без истории:10271
  Кривая без истории:10272
  Кривая без истории:10273
  Кривая без истории:10274
  Кривая без истории:10275
  Кривая без истории:10276
  Кривая без истории:10277
  Кривая без истории:10278
  Кривая без истории:10279
  Кривая без истории:10280
  Кривая без истории:10281
  Кривая без истории:10282
  Кривая без истории:10283
  Кривая без истории:10284
  Кривая без истории:10285
  Кривая без истории:10286
  Кривая без истории:10287
  Кривая без истории:10288
  Кривая без истории:10289
  Кривая без истории:10290
  Кривая без истории:10291
  Кривая без истории:10292
  Кривая без истории:10293
  Кривая без истории:10294
  Кривая без истории:10295
  Кривая без истории:10296
  Кривая без истории:10297
  Кривая без истории:10298
  Кривая без истории:10299
  Кривая без истории:10300
  Кривая без истории:10301
  Кривая без истории:10302
  Кривая без истории:10303
  Кривая без истории:10304
  Кривая без истории:10305
  Кривая без истории:10306
  Кривая без истории:10307
  Кривая без истории:10308
  Кривая без истории:10309
  Кривая без истории:10310
  Кривая без истории:10311
  Кривая без истории:10312
  Кривая без истории:10313
  Кривая без истории:10314
  Кривая без истории:10315
  Кривая без истории:10316
  Кривая без истории:10317
  Кривая без истории:10318
  Кривая без истории:10319
  Кривая без истории:10320
  Кривая без истории:10321
  Кривая без истории:10322
  Кривая без истории:10323
  Кривая без истории:10324
  Кривая без истории:10325
  Кривая без истории:10326
  Кривая без истории:10327
  Кривая без истории:10328
  Кривая без истории:10329
  Кривая без истории:10330
  Кривая без истории:10331
  Кривая без истории:10332
  Кривая без истории:10333
  Кривая без истории:10334
  Кривая без истории:10335
  Кривая без истории:10336
  Кривая без истории:10337
  Кривая без истории:10338
  Кривая без истории:10339
  Кривая без истории:10340
  Кривая без истории:10341
  Кривая без истории:10342
  Кривая без истории:10343
  Кривая без истории:10344
  Кривая без истории:10345
  Кривая без истории:10346
  Кривая без истории:10347
  Кривая без истории:10348
  Кривая без истории:10349
  Кривая без истории:10350
  Кривая без истории:10351
  Кривая без истории:10352
  Кривая без истории:10353
  Кривая без истории:10354
  Кривая без истории:10355
  Кривая без истории:10356
  Кривая без истории:10357
  Кривая без истории:10358
  Кривая без истории:10359
  Кривая без истории:10360
  Кривая без истории:10361
  Кривая без истории:10362
  Кривая без истории:10363
  Кривая без истории:10364
  Кривая без истории:10365
  Кривая без истории:10366
  Кривая без истории:10367
  Кривая без истории:10368
  Кривая без истории:10369
  Кривая без истории:10370
  Кривая без истории:10371
  Кривая без истории:10372
  Кривая без истории:10373
  Кривая без истории:10374
  Кривая без истории:10375
  Кривая без истории:10376
  Кривая без истории:10377
  Кривая без истории:10378
  Кривая без истории:10379
  Кривая без истории:10380
  Кривая без истории:10381
  Кривая без истории:10382
  Кривая без истории:10383
  Кривая без истории:10384
  Кривая без истории:10385
  Кривая без истории:10386
  Кривая без истории:10387
  Кривая без истории:10388
  Кривая без истории:10389
  Кривая без истории:10390
  Кривая без истории:10391
  Кривая без истории:10392
  Кривая без истории:10393
  Кривая без истории:10394
  Кривая без истории:10395
  Кривая без истории:10396
  Кривая без истории:10397
  Кривая без истории:10398
  Кривая без истории:10399
  Кривая без истории:10400
  Кривая без истории:10401
  Кривая без истории:10402
  Кривая без истории:10403
  Кривая без истории:10404
  Кривая без истории:10405
  Кривая без истории:10406
  Кривая без истории:10407
  Кривая без истории:10408
  Кривая без истории:10409
  Кривая без истории:10410
  Кривая без истории:10411
  Кривая без истории:10412
  Кривая без истории:10413
  Кривая без истории:10414
  Кривая без истории:10415
  Кривая без истории:10416
  Кривая без истории:10417
  Кривая без истории:10418
  Кривая без истории:10419
  Кривая без истории:10420
  Кривая без истории:10421
  Кривая без истории:10422
  Кривая без истории:10423
  Кривая без истории:10424
  Кривая без истории:10425
  Кривая без истории:10426
  Кривая без истории:10427
  Кривая без истории:10428
  Кривая без истории:10429
  Кривая без истории:10430
  Кривая без истории:10431
  Кривая без истории:10432
  Кривая без истории:10433
  Кривая без истории:10434
  Кривая без истории:10435
  Кривая без истории:10436
  Кривая без истории:10437
  Кривая без истории:10438
  Кривая без истории:10439
  Кривая без истории:10440
  Кривая без истории:10441
  Кривая без истории:10442
  Кривая без истории:10443
  Кривая без истории:10444
  Кривая без истории:10445
  Кривая без истории:10446
  Кривая без истории:10447
  Кривая без истории:10448
  Кривая без истории:10449
  Кривая без истории:10450
  Кривая без истории:10451
  Кривая без истории:10452
  Кривая без истории:10453
  Кривая без истории:10454
  Кривая без истории:10455
  Кривая без истории:10456
  Кривая без истории:10457
  Кривая без истории:10458
  Кривая без истории:10459
  Кривая без истории:10460
  Кривая без истории:10461
  Кривая без истории:10462
  Кривая без истории:10463
  Кривая без истории:10464
  Кривая без истории:10465
  Кривая без истории:10466
  Кривая без истории:10467
  Кривая без истории:10468
  Кривая без истории:10469
  Кривая без истории:10470
  Кривая без истории:10471
  Кривая без истории:10472
  Кривая без истории:10473
  Кривая без истории:10474
  Кривая без истории:10475
  Кривая без истории:10476
  Кривая без истории:10477
  Кривая без истории:10478
  Кривая без истории:10479
  Кривая без истории:10480
  Кривая без истории:10481
  Кривая без истории:10482
  Кривая без истории:10483
  Кривая без истории:10484
  Кривая без истории:10485
  Кривая без истории:10486
  Кривая без истории:10487
  Кривая без истории:10488
  Кривая без истории:10489
  Кривая без истории:10490
  Кривая без истории:10491
  Кривая без истории:10492
  Кривая без истории:10493
  Кривая без истории:10494
  Кривая без истории:10495
  Кривая без истории:10496
  Кривая без истории:10497
  Кривая без истории:10498
  Кривая без истории:10499
  Кривая без истории:10500
  Кривая без истории:10501
  Кривая без истории:10502
  Кривая без истории:10503
  Кривая без истории:10504
  Кривая без истории:10505
  Кривая без истории:10506
  Кривая без истории:10507
  Кривая без истории:10508
  Кривая без истории:10509
  Кривая без истории:10510
  Кривая без истории:10511
  Кривая без истории:10512
  Кривая без истории:10513
  Кривая без истории:10514
  Кривая без истории:10515
  Кривая без истории:10516
  Кривая без истории:10517
  Кривая без истории:10518
  Кривая без истории:10519
  Кривая без истории:10520
  Кривая без истории:10521
  Кривая без истории:10522
  Кривая без истории:10523
  Кривая без истории:10524
  Кривая без истории:10525
  Кривая без истории:10526
  Кривая без истории:10527
  Кривая без истории:10528
  Кривая без истории:10529
  Кривая без истории:10530
  Кривая без истории:10531
  Кривая без истории:10532
  Кривая без истории:10533
  Кривая без истории:10534
  Кривая без истории:10535
  Кривая без истории:10536
  Кривая без истории:10537
  Кривая без истории:10538
  Кривая без истории:10539
  Кривая без истории:10540
  Кривая без истории:10541
  Кривая без истории:10542
  Кривая без истории:10543
  Кривая без истории:10544
  Кривая без истории:10545
  Кривая без истории:10546
  Кривая без истории:10547
  Кривая без истории:10548
  Кривая без истории:10549
  Кривая без истории:10550
  Кривая без истории:10551
  Кривая без истории:10552
  Кривая без истории:10553
  Кривая без истории:10554
  Кривая без истории:10555
  Кривая без истории:10556
  Кривая без истории:10557
  Кривая без истории:10558
  Кривая без истории:10559
  Кривая без истории:10560
  Кривая без истории:10561
  Кривая без истории:10562
  Кривая без истории:10563
  Кривая без истории:10564
  Кривая без истории:10565
  Кривая без истории:10566
  Кривая без истории:10567
  Кривая без истории:10568
  Кривая без истории:10569
  Кривая без истории:10570
  Кривая без истории:10571
  Кривая без истории:10572
  Кривая без истории:10573
  Кривая без истории:10574
  Кривая без истории:10575
  Кривая без истории:10576
  Кривая без истории:10577
  Кривая без истории:10578
  Кривая без истории:10579
  Кривая без истории:10580
  Кривая без истории:10581
  Кривая без истории:10582
  Кривая без истории:10583
  Кривая без истории:10584
  Кривая без истории:10585
  Кривая без истории:10586
  Кривая без истории:10587
  Кривая без истории:10588
  Кривая без истории:10589
  Кривая без истории:10590
  Кривая без истории:10591
  Кривая без истории:10592
  Кривая без истории:10593
  Кривая без истории:10594
  Кривая без истории:10595
  Кривая без истории:10596
  Кривая без истории:10597
  Кривая без истории:10598
  Кривая без истории:10599
  Кривая без истории:10600
  Кривая без истории:10601
  Кривая без истории:10602
  Кривая без истории:10603
  Кривая без истории:10604
  Кривая без истории:10605
  Кривая без истории:10606
  Кривая без истории:10607
  Кривая без истории:10608
  Кривая без истории:10609
  Кривая без истории:10610
  Кривая без истории:10611
  Кривая без истории:10612
  Кривая без истории:10613
  Кривая без истории:10614
  Кривая без истории:10615
  Кривая без истории:10616
  Кривая без истории:10617
  Кривая без истории:10618
  Кривая без истории:10619
  Кривая без истории:10620
  Кривая без истории:10621
  Кривая без истории:10622
  Кривая без истории:10623
  Кривая без истории:10624
  Кривая без истории:10625
  Кривая без истории:10626
  Кривая без истории:10627
  Кривая без истории:10628
  Кривая без истории:10629
  Кривая без истории:10630
  Кривая без истории:10631
  Кривая без истории:10632
  Кривая без истории:10633
  Кривая без истории:10634
  Кривая без истории:10635
  Кривая без истории:10636
  Кривая без истории:10637
  Кривая без истории:10638
  Кривая без истории:10639
  Кривая без истории:10640
  Кривая без истории:10641
  Кривая без истории:10642
  Кривая без истории:10643
  Кривая без истории:10644
  Кривая без истории:10645
  Кривая без истории:10646
  Кривая без истории:10647
  Кривая без истории:10648
  Кривая без истории:10649
  Кривая без истории:10650
  Кривая без истории:10651
  Кривая без истории:10652
  Кривая без истории:10653
  Кривая без истории:10654
  Кривая без истории:10655
  Кривая без истории:10656
  Кривая без истории:10657
  Кривая без истории:10658
  Кривая без истории:10659
  Кривая без истории:10660
  Кривая без истории:10661
  Кривая без истории:10662
  Кривая без истории:10663
  Кривая без истории:10664
  Кривая без истории:10665
  Кривая без истории:10666
  Кривая без истории:10667
  Кривая без истории:10668
  Кривая без истории:10669
  Кривая без истории:10670
  Кривая без истории:10671
  Кривая без истории:10672
  Кривая без истории:10673
  Кривая без истории:10674
  Кривая без истории:10675
  Кривая без истории:10676
  Кривая без истории:10677
  Кривая без истории:10678
  Кривая без истории:10679
  Кривая без истории:10680
  Кривая без истории:10681
  Кривая без истории:10682
  Кривая без истории:10683
  Кривая без истории:10684
  Кривая без истории:10685
  Кривая без истории:10686
  Кривая без истории:10687
  Кривая без истории:10688
  Кривая без истории:10689
  Кривая без истории:10690
  Кривая без истории:10691
  Кривая без истории:10692
  Кривая без истории:10693
  Кривая без истории:10694
  Кривая без истории:10695
  Кривая без истории:10696
  Кривая без истории:10697
  Кривая без истории:10698
  Кривая без истории:10699
  Кривая без истории:10700
  Кривая без истории:10701
  Кривая без истории:10702
  Кривая без истории:10703
  Кривая без истории:10704
  Кривая без истории:10705
  Кривая без истории:10706
  Кривая без истории:10707
  Кривая без истории:10708
  Кривая без истории:10709
  Кривая без истории:10710
  Кривая без истории:10711
  Кривая без истории:10712
  Кривая без истории:10713
  Кривая без истории:10714
  Кривая без истории:10715
  Кривая без истории:10716
  Кривая без истории:10717
  Кривая без истории:10718
  Кривая без истории:10719
  Кривая без истории:10720
  Кривая без истории:10721
  Кривая без истории:10722
  Кривая без истории:10723
  Кривая без истории:10724
  Кривая без истории:10725
  Кривая без истории:10726
  Кривая без истории:10727
  Кривая без истории:10728
  Кривая без истории:10729
  Кривая без истории:10730
  Кривая без истории:10731
  Кривая без истории:10732
  Кривая без истории:10733
  Кривая без истории:10734
  Кривая без истории:10735
  Кривая без истории:10736
  Кривая без истории:10737
  Кривая без истории:10738
  Кривая без истории:10739
  Кривая без истории:10740
  Кривая без истории:10741
  Кривая без истории:10742
  Кривая без истории:10743
  Кривая без истории:10744
  Кривая без истории:10745
  Кривая без истории:10746
  Кривая без истории:10747
  Кривая без истории:10748
  Кривая без истории:10749
  Кривая без истории:10750
  Кривая без истории:10751
  Кривая без истории:10752
  Кривая без истории:10753
  Кривая без истории:10754
  Кривая без истории:10755
  Кривая без истории:10756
